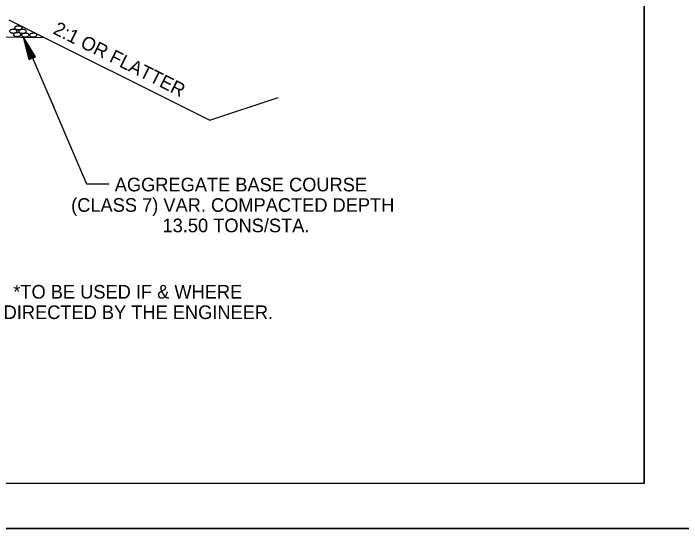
# Model space of a CAD drawing. Extents: x 2263886 to 2266026, y -3122850 to -3121850.
# Drawn here: x 2265328.89 to 2265358.3, y -3122443.82 to -3122421.13 of the extents above; entities that cross this region are included whole.
import ezdxf

# ---------------------------------------------------------------- set-up
doc = ezdxf.new("R2010")
doc.units = 0
for name, color, linetype in [('_CIVIL_CONSTRUCTION', 7, 'Continuous'), ('R_Border Notes', 7, 'Continuous'), ('R_Border Prem', 7, 'Continuous'), ('R_Draft', 7, 'Continuous')]:
    doc.layers.add(name, color=color, linetype=linetype)

msp = doc.modelspace()

# ---------------------------------------------------------------- linework, layer by layer
at = {"layer": '_CIVIL_CONSTRUCTION'}
msp.add_line((2265192.355, -3122443.817), (2265359.022, -3122443.817), dxfattribs=at)
for points in [[(2265192.352, -3122337.151), (2265359.022, -3122337.151), (2265359.022, -3122443.82), (2265192.352, -3122443.82)], [(2265315.516, -3122339.098), (2265315.516, -3122344.038), (2265333.382, -3122344.038), (2265333.382, -3122345.498), (2265344.981, -3122345.498), (2265344.981, -3122357.664), (2265356.646, -3122357.664), (2265356.646, -3122441.828), (2265198.556, -3122441.828), (2265198.556, -3122339.098)]]:
    msp.add_lwpolyline(points, close=True, dxfattribs=at)
at = {"layer": 'R_Border Notes'}
for p, q in [((2265328.698, -3122421.416), (2265337.54, -3122425.837)), ((2265326.695, -3122422.129), (2265330.267, -3122422.201)), ((2265337.54, -3122425.837), (2265340.54, -3122424.837))]:
    msp.add_line(p, q, dxfattribs=at)
at = {"layer": 'R_Border Prem'}
for p, q in [((2265329.343, -3122422.182), (2265330.097, -3122423.937)), ((2265329.593, -3122423.162), (2265329.343, -3122422.182)), ((2265329.869, -3122423.046), (2265329.343, -3122422.182)), ((2265329.616, -3122423.152), (2265329.408, -3122422.336)), ((2265329.846, -3122423.055), (2265329.408, -3122422.336)), ((2265329.823, -3122423.065), (2265329.474, -3122422.495)), ((2265329.639, -3122423.142), (2265329.474, -3122422.495)), ((2265329.662, -3122423.133), (2265329.539, -3122422.648)), ((2265329.8, -3122423.075), (2265329.539, -3122422.648)), ((2265329.593, -3122423.162), (2265329.869, -3122423.046)), ((2265329.776, -3122423.085), (2265329.605, -3122422.804)), ((2265329.686, -3122423.123), (2265329.605, -3122422.804)), ((2265329.753, -3122423.095), (2265329.67, -3122422.958)), ((2265329.709, -3122423.113), (2265329.67, -3122422.958)), ((2265330.097, -3122423.937), (2265332.116, -3122428.633)), ((2265330.376, -3122424.585), (2265330.67, -3122425.268)), ((2265332.116, -3122428.633), (2265333.116, -3122428.633))]:
    msp.add_line(p, q, dxfattribs=at)
for points in [[(2265328.736, -3122421.884), (2265328.729, -3122421.895), (2265328.726, -3122421.905), (2265328.723, -3122421.918), (2265328.725, -3122421.926), (2265328.731, -3122421.939), (2265328.739, -3122421.949), (2265328.753, -3122421.96), (2265328.762, -3122421.968), (2265328.77, -3122421.971), (2265328.787, -3122421.98), (2265328.817, -3122421.989), (2265328.862, -3122421.997), (2265328.908, -3122421.997), (2265328.957, -3122421.99), (2265329.006, -3122421.974), (2265329.034, -3122421.955), (2265329.052, -3122421.935), (2265329.056, -3122421.918), (2265329.056, -3122421.903), (2265329.051, -3122421.887), (2265329.045, -3122421.879), (2265329.036, -3122421.871), (2265329.024, -3122421.864), (2265329.01, -3122421.855), (2265328.999, -3122421.851), (2265328.977, -3122421.843), (2265328.946, -3122421.838), (2265328.903, -3122421.836), (2265328.872, -3122421.838), (2265328.84, -3122421.841), (2265328.823, -3122421.845), (2265328.8, -3122421.85), (2265328.774, -3122421.859), (2265328.759, -3122421.867), (2265328.741, -3122421.88), (2265328.733, -3122421.887)], [(2265328.96, -3122421.736), (2265328.953, -3122421.747), (2265328.95, -3122421.757), (2265328.947, -3122421.77), (2265328.949, -3122421.778), (2265328.955, -3122421.791), (2265328.963, -3122421.801), (2265328.977, -3122421.812), (2265328.986, -3122421.82), (2265328.994, -3122421.823), (2265329.011, -3122421.832), (2265329.041, -3122421.841), (2265329.086, -3122421.849), (2265329.132, -3122421.849), (2265329.181, -3122421.842), (2265329.23, -3122421.826), (2265329.258, -3122421.807), (2265329.276, -3122421.787), (2265329.28, -3122421.77), (2265329.28, -3122421.755), (2265329.275, -3122421.739), (2265329.269, -3122421.731), (2265329.26, -3122421.723), (2265329.248, -3122421.716), (2265329.234, -3122421.707), (2265329.223, -3122421.703), (2265329.201, -3122421.695), (2265329.17, -3122421.69), (2265329.127, -3122421.688), (2265329.096, -3122421.69), (2265329.064, -3122421.693), (2265329.047, -3122421.697), (2265329.024, -3122421.702), (2265328.998, -3122421.711), (2265328.983, -3122421.719), (2265328.965, -3122421.732), (2265328.957, -3122421.739)], [(2265329.139, -3122421.892), (2265329.132, -3122421.903), (2265329.129, -3122421.913), (2265329.126, -3122421.926), (2265329.128, -3122421.934), (2265329.134, -3122421.947), (2265329.142, -3122421.957), (2265329.156, -3122421.968), (2265329.165, -3122421.976), (2265329.173, -3122421.979), (2265329.19, -3122421.988), (2265329.22, -3122421.997), (2265329.265, -3122422.005), (2265329.311, -3122422.005), (2265329.36, -3122421.998), (2265329.409, -3122421.982), (2265329.437, -3122421.963), (2265329.455, -3122421.943), (2265329.459, -3122421.926), (2265329.459, -3122421.911), (2265329.454, -3122421.895), (2265329.448, -3122421.887), (2265329.439, -3122421.879), (2265329.427, -3122421.872), (2265329.413, -3122421.863), (2265329.402, -3122421.859), (2265329.38, -3122421.851), (2265329.349, -3122421.846), (2265329.306, -3122421.844), (2265329.275, -3122421.846), (2265329.243, -3122421.849), (2265329.226, -3122421.853), (2265329.203, -3122421.858), (2265329.177, -3122421.867), (2265329.162, -3122421.875), (2265329.144, -3122421.888), (2265329.136, -3122421.895)], [(2265328.908, -3122422.032), (2265328.901, -3122422.043), (2265328.898, -3122422.053), (2265328.895, -3122422.066), (2265328.897, -3122422.074), (2265328.903, -3122422.087), (2265328.911, -3122422.097), (2265328.925, -3122422.108), (2265328.934, -3122422.116), (2265328.942, -3122422.119), (2265328.959, -3122422.128), (2265328.989, -3122422.137), (2265329.034, -3122422.145), (2265329.08, -3122422.145), (2265329.129, -3122422.138), (2265329.178, -3122422.122), (2265329.206, -3122422.103), (2265329.224, -3122422.083), (2265329.228, -3122422.066), (2265329.228, -3122422.051), (2265329.223, -3122422.035), (2265329.217, -3122422.027), (2265329.208, -3122422.019), (2265329.196, -3122422.012), (2265329.182, -3122422.003), (2265329.171, -3122421.999), (2265329.149, -3122421.991), (2265329.118, -3122421.986), (2265329.075, -3122421.984), (2265329.044, -3122421.986), (2265329.012, -3122421.989), (2265328.995, -3122421.993), (2265328.972, -3122421.998), (2265328.946, -3122422.007), (2265328.931, -3122422.015), (2265328.913, -3122422.028), (2265328.905, -3122422.035)], [(2265329.261, -3122422.056), (2265329.254, -3122422.067), (2265329.251, -3122422.077), (2265329.248, -3122422.09), (2265329.25, -3122422.098), (2265329.256, -3122422.111), (2265329.264, -3122422.121), (2265329.278, -3122422.132), (2265329.287, -3122422.14), (2265329.295, -3122422.143), (2265329.312, -3122422.152), (2265329.342, -3122422.161), (2265329.387, -3122422.169), (2265329.433, -3122422.169), (2265329.482, -3122422.162), (2265329.531, -3122422.146), (2265329.559, -3122422.127), (2265329.577, -3122422.107), (2265329.581, -3122422.09), (2265329.581, -3122422.075), (2265329.576, -3122422.059), (2265329.57, -3122422.051), (2265329.561, -3122422.043), (2265329.549, -3122422.036), (2265329.535, -3122422.027), (2265329.524, -3122422.023), (2265329.502, -3122422.015), (2265329.471, -3122422.01), (2265329.428, -3122422.008), (2265329.397, -3122422.01), (2265329.365, -3122422.013), (2265329.348, -3122422.017), (2265329.325, -3122422.022), (2265329.299, -3122422.031), (2265329.284, -3122422.039), (2265329.266, -3122422.052), (2265329.258, -3122422.059)], [(2265329.61, -3122422.056), (2265329.603, -3122422.067), (2265329.6, -3122422.077), (2265329.597, -3122422.09), (2265329.599, -3122422.098), (2265329.605, -3122422.111), (2265329.613, -3122422.121), (2265329.627, -3122422.132), (2265329.636, -3122422.14), (2265329.644, -3122422.143), (2265329.661, -3122422.152), (2265329.691, -3122422.161), (2265329.736, -3122422.169), (2265329.782, -3122422.169), (2265329.831, -3122422.162), (2265329.88, -3122422.146), (2265329.908, -3122422.127), (2265329.926, -3122422.107), (2265329.93, -3122422.09), (2265329.93, -3122422.075), (2265329.925, -3122422.059), (2265329.919, -3122422.051), (2265329.91, -3122422.043), (2265329.898, -3122422.036), (2265329.884, -3122422.027), (2265329.873, -3122422.023), (2265329.851, -3122422.015), (2265329.82, -3122422.01), (2265329.777, -3122422.008), (2265329.746, -3122422.01), (2265329.714, -3122422.013), (2265329.697, -3122422.017), (2265329.674, -3122422.022), (2265329.648, -3122422.031), (2265329.633, -3122422.039), (2265329.615, -3122422.052), (2265329.607, -3122422.059)]]:
    msp.add_spline(points, degree=3, dxfattribs=at)
at = {"layer": 'R_Draft'}
for q in [(2265356.646, -3122339.098), (2265198.556, -3122441.828)]:
    msp.add_line((2265356.646, -3122441.828), q, dxfattribs=at)

# ---------------------------------------------------------------- texts
at = {"layer": 'R_Border Prem'}
msp.add_text('2:1 OR FLATTER', height=0.6, rotation=333.435, dxfattribs=at).set_placement((2265330.601, -3122422.004))
for s, p in [('AGGREGATE BASE COURSE', (2265333.355, -3122428.969)), ('(CLASS 7) VAR. COMPACTED DEPTH', (2265331.436, -3122429.869)), ('13.50 TONS/STA.', (2265335.457, -3122430.769)), ('*TO BE USED IF & WHERE', (2265328.89, -3122433.69)), ('DIRECTED BY THE ENGINEER.', (2265328.465, -3122434.59))]:
    msp.add_text(s, height=0.6, dxfattribs=at).set_placement(p)

doc.saveas('drawing.dxf')
